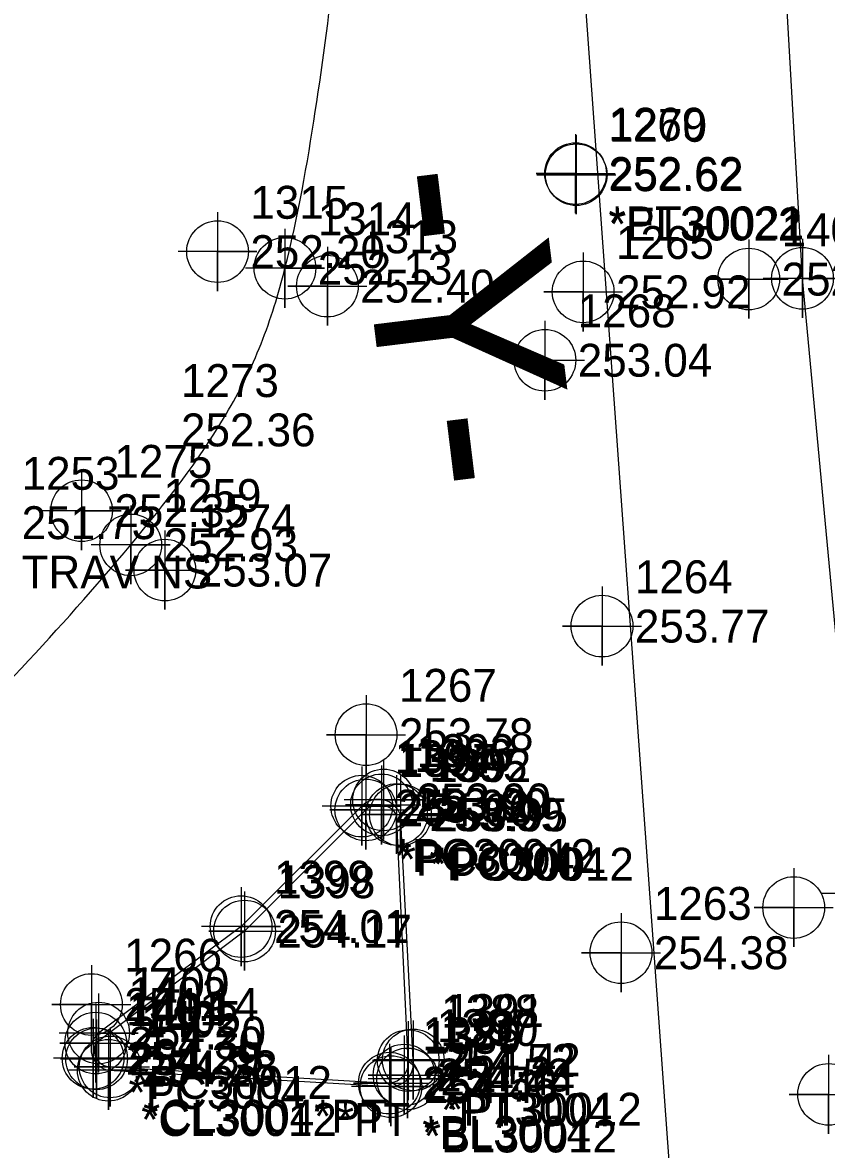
# Model space of a CAD drawing. Extents: x 2130621 to 2131998, y 642516 to 644503.
# Drawn here: x 2131200.6 to 2131261.7, y 643203.1 to 643288.8 of the extents above; entities that cross this region are included whole.
import ezdxf

# ---------------------------------------------------------------- set-up
doc = ezdxf.new("R2010")
doc.units = 0
for name, color, linetype in [('CTL Secondary Horizontal and Vertical Cogo Comment', 7, 'Continuous'), ('CTL Secondary Horizontal and Vertical Cogo Elevation', 7, 'Continuous'), ('CTL Secondary Horizontal and Vertical Cogo Number', 7, 'Continuous'), ('Exist Guardrail Cogo Elevation', 7, 'Continuous'), ('Exist Guardrail Cogo Number', 7, 'Continuous'), ('Exist Guardrail Cogo Point CELL', 7, 'Continuous'), ('Exist Roads Curbs', 7, 'Continuous'), ('Exist Roads Curbs Cogo Comment', 7, 'Continuous'), ('Exist Roads Curbs Cogo Elevation', 7, 'Continuous'), ('Exist Roads Curbs Cogo Number', 7, 'Continuous'), ('Exist Roads Curbs Cogo Point CELL', 7, 'Continuous'), ('Exist Roads EOP', 7, 'Continuous'), ('Exist Roads EOP Cogo Comment', 7, 'Continuous'), ('Exist Roads EOP Cogo Elevation', 7, 'Continuous'), ('Exist Roads EOP Cogo Number', 7, 'Continuous'), ('Exist Roads EOP Cogo Point CELL', 7, 'Continuous'), ('Exist Roads EOT Cogo Comment', 7, 'Continuous'), ('Exist Roads EOT Cogo Elevation', 7, 'Continuous'), ('Exist Roads EOT Cogo Number', 7, 'Continuous'), ('Exist Roads EOT Cogo Point CELL', 7, 'Continuous'), ('Exist Utilities Other Traffic Signal Box Cogo Elevation', 7, 'Continuous'), ('Exist Utilities Other Traffic Signal Box Cogo Number', 7, 'Continuous'), ('Prop Horizontal Alignment', 7, 'Continuous')]:
    doc.layers.add(name, color=color, linetype=linetype)

msp = doc.modelspace()

# ---------------------------------------------------------------- linework, layer by layer
at = {"layer": 'Exist Guardrail Cogo Point CELL'}
for points in [[(2131215.409, 643274.354), (2131215.409, 643268.354), (2131215.409, 643271.354), (2131218.409, 643271.354), (2131212.409, 643271.354)], [(2131205.072, 643254.664), (2131205.072, 643248.664), (2131205.072, 643251.664), (2131208.072, 643251.664), (2131202.072, 643251.664)]]:
    msp.add_lwpolyline(points, dxfattribs=at)
for centre in [(2131215.409, 643271.354), (2131205.072, 643251.664)]:
    msp.add_circle(centre, 2.344, dxfattribs=at)
at = {"layer": 'Exist Roads Curbs'}
for points in [[(2131226.681, 643228.925), (2131217.467, 643219.716), (2131206.148, 643211.206)], [(2131226.681, 643228.925), (2131226.681, 643228.925)], [(2131229.912, 643209.875), (2131229.021, 643228.574)], [(2131207.247, 643209.393), (2131228.474, 643208.158)]]:
    msp.add_lwpolyline(points, dxfattribs=at)
for centre, major_axis, ratio, start_param, end_param in [((2131227.705, 643227.782), (-1.486, 0.387), 0.999933, 3.938071, 5.698116), ((2131207.308, 643210.669), (1.277, -0.055), 0.999046, 2.750218, 4.707768), ((2131228.321, 643209.747), (-0.142, 1.59), 0.999747, 3.14801, 4.70398)]:
    msp.add_ellipse(centre, major_axis=major_axis, ratio=ratio, start_param=start_param, end_param=end_param, dxfattribs=at)
at = {"layer": 'Exist Roads Curbs Cogo Point CELL'}
for points in [[(2131226.681, 643231.925), (2131226.681, 643225.925), (2131226.681, 643228.925), (2131223.951, 643228.925), (2131229.681, 643228.925)], [(2131227.876, 643232.308), (2131227.876, 643226.308), (2131227.876, 643229.308), (2131225.146, 643229.308), (2131230.876, 643229.308)], [(2131229.021, 643231.574), (2131229.021, 643225.574), (2131229.021, 643228.574), (2131226.291, 643228.574), (2131232.021, 643228.574)], [(2131217.467, 643222.716), (2131217.467, 643216.716), (2131217.467, 643219.716), (2131214.737, 643219.716), (2131220.467, 643219.716)], [(2131206.148, 643214.206), (2131206.148, 643208.206), (2131206.148, 643211.206), (2131203.418, 643211.206), (2131209.148, 643211.206)], [(2131206.214, 643213.008), (2131206.214, 643207.008), (2131206.214, 643210.008), (2131203.484, 643210.008), (2131209.214, 643210.008)], [(2131229.912, 643212.875), (2131229.912, 643206.875), (2131229.912, 643209.875), (2131227.182, 643209.875), (2131232.912, 643209.875)], [(2131207.247, 643212.393), (2131207.247, 643206.393), (2131207.247, 643209.393), (2131204.517, 643209.393), (2131210.247, 643209.393)], [(2131228.474, 643211.158), (2131228.474, 643205.158), (2131228.474, 643208.158), (2131225.744, 643208.158), (2131231.474, 643208.158)], [(2131229.587, 643211.774), (2131229.587, 643205.774), (2131229.587, 643208.774), (2131226.857, 643208.774), (2131232.587, 643208.774)]]:
    msp.add_lwpolyline(points, dxfattribs=at)
for centre in [(2131227.876, 643229.308), (2131226.681, 643228.925), (2131229.021, 643228.574), (2131217.467, 643219.716), (2131206.148, 643211.206), (2131206.214, 643210.008), (2131229.912, 643209.875), (2131207.247, 643209.393), (2131229.587, 643208.774), (2131228.474, 643208.158)]:
    msp.add_circle(centre, 2.344, dxfattribs=at)
at = {"layer": 'Exist Roads EOP'}
for points in [[(2131264.271, 643222.565), (2131259.876, 643269.325), (2131257.02, 643319.404), (2131254.256, 643369.65), (2131250.078, 643419.419), (2131246.151, 643469.029), (2131240.838, 643519.127), (2131234.367, 643568.558), (2131226.332, 643620.181), (2131217.027, 643668.712), (2131205.621, 643717.607), (2131192.058, 643767.26), (2131177.971, 643815.091), (2131162.291, 643862.934), (2131145.36, 643910.849), (2131126.911, 643957.292), (2131112.369, 643996.123)], [(2131226.375, 643229.212), (2131217.199, 643220.058), (2131206.365, 643211.964)], [(2131226.375, 643229.212), (2131226.375, 643229.212)], [(2131230.287, 643209.923), (2131229.316, 643228.547)], [(2131207.109, 643209.139), (2131228.592, 643207.891)]]:
    msp.add_lwpolyline(points, dxfattribs=at)
for centre, major_axis, ratio, start_param, end_param in [((2131227.632, 643227.936), (-1.79, 0.066), 0.998981, 3.527087, 5.526683), ((2131207.41, 643210.728), (0.839, -1.385), 0.997672, 3.299661, 5.55015), ((2131228.533, 643209.663), (1.386, 1.107), 0.999842, 4.071754, 5.755689)]:
    msp.add_ellipse(centre, major_axis=major_axis, ratio=ratio, start_param=start_param, end_param=end_param, dxfattribs=at)
msp.add_spline([(2131166.249, 643216.695), (2131171.813, 643218.724), (2131182.371, 643223.973), (2131191.812, 643231.149), (2131200.501, 643239.699), (2131208.807, 643249.07), (2131216.067, 643259.003), (2131218.719, 643264.347), (2131220.536, 643270.096), (2131222.844, 643282.008), (2131224.358, 643293.924), (2131224.876, 643317.79), (2131222.063, 643367.672), (2131218.545, 643416.811), (2131214.319, 643466.346), (2131209.174, 643515.667), (2131202.794, 643565.155), (2131195.047, 643613.994), (2131186.401, 643662.476), (2131176.011, 643711.405), (2131164.615, 643759.89), (2131151.874, 643807.853), (2131137.855, 643855.407), (2131122.573, 643902.857), (2131105.962, 643949.486), (2131091.535, 643988.044)], degree=3, dxfattribs=at)
at = {"layer": 'Exist Roads EOP Cogo Point CELL'}
for points in [[(2131220.536, 643273.096), (2131220.536, 643267.096), (2131220.536, 643270.096), (2131223.536, 643270.096), (2131217.536, 643270.096)], [(2131259.876, 643272.325), (2131259.876, 643266.325), (2131259.876, 643269.325), (2131262.876, 643269.325), (2131256.876, 643269.325)], [(2131208.807, 643252.07), (2131208.807, 643246.07), (2131208.807, 643249.07), (2131211.807, 643249.07), (2131205.807, 643249.07)], [(2131228.036, 643232.68), (2131228.036, 643226.68), (2131228.036, 643229.68), (2131231.036, 643229.68), (2131225.036, 643229.68)], [(2131226.375, 643232.212), (2131226.375, 643226.212), (2131226.375, 643229.212), (2131229.375, 643229.212), (2131223.375, 643229.212)], [(2131229.316, 643231.547), (2131229.316, 643225.547), (2131229.316, 643228.547), (2131232.316, 643228.547), (2131226.316, 643228.547)], [(2131264.271, 643225.565), (2131264.271, 643219.565), (2131264.271, 643222.565), (2131267.271, 643222.565), (2131261.271, 643222.565)], [(2131217.199, 643223.058), (2131217.199, 643217.058), (2131217.199, 643220.058), (2131220.199, 643220.058), (2131214.199, 643220.058)], [(2131206.365, 643214.964), (2131206.365, 643208.964), (2131206.365, 643211.964), (2131209.365, 643211.964), (2131203.365, 643211.964)], [(2131205.947, 643213.044), (2131205.947, 643207.044), (2131205.947, 643210.044), (2131208.947, 643210.044), (2131202.947, 643210.044)], [(2131230.287, 643212.923), (2131230.287, 643206.923), (2131230.287, 643209.923), (2131233.287, 643209.923), (2131227.287, 643209.923)], [(2131207.109, 643212.139), (2131207.109, 643206.139), (2131207.109, 643209.139), (2131210.109, 643209.139), (2131204.109, 643209.139)], [(2131229.857, 643211.484), (2131229.857, 643205.484), (2131229.857, 643208.484), (2131232.857, 643208.484), (2131226.857, 643208.484)], [(2131228.592, 643210.891), (2131228.592, 643204.891), (2131228.592, 643207.891), (2131231.592, 643207.891), (2131225.592, 643207.891)]]:
    msp.add_lwpolyline(points, dxfattribs=at)
for centre in [(2131220.536, 643270.096), (2131259.876, 643269.325), (2131208.807, 643249.07), (2131228.036, 643229.68), (2131226.375, 643229.212), (2131229.316, 643228.547), (2131217.199, 643220.058), (2131206.365, 643211.964), (2131205.947, 643210.044), (2131230.287, 643209.923), (2131207.109, 643209.139), (2131228.592, 643207.891), (2131229.857, 643208.484)]:
    msp.add_circle(centre, 2.344, dxfattribs=at)
at = {"layer": 'Exist Roads EOT Cogo Point CELL'}
for points in [[(2131242.626, 643280.289), (2131242.626, 643274.289), (2131242.626, 643277.289), (2131239.626, 643277.289), (2131245.626, 643277.289)], [(2131242.676, 643280.201), (2131242.676, 643274.201), (2131242.676, 643277.201), (2131239.676, 643277.201), (2131245.676, 643277.201)], [(2131255.789, 643272.267), (2131255.789, 643266.267), (2131255.789, 643269.267), (2131252.789, 643269.267), (2131258.789, 643269.267)], [(2131223.758, 643271.731), (2131223.758, 643265.731), (2131223.758, 643268.731), (2131220.758, 643268.731), (2131226.758, 643268.731)], [(2131243.203, 643271.297), (2131243.203, 643265.297), (2131243.203, 643268.297), (2131240.203, 643268.297), (2131246.203, 643268.297)], [(2131240.295, 643266.099), (2131240.295, 643260.099), (2131240.295, 643263.099), (2131237.295, 643263.099), (2131243.295, 643263.099)], [(2131211.406, 643250.15), (2131211.406, 643244.15), (2131211.406, 643247.15), (2131208.406, 643247.15), (2131214.406, 643247.15)], [(2131244.636, 643245.893), (2131244.636, 643239.893), (2131244.636, 643242.893), (2131241.636, 643242.893), (2131247.636, 643242.893)], [(2131226.702, 643237.643), (2131226.702, 643231.643), (2131226.702, 643234.643), (2131223.702, 643234.643), (2131229.702, 643234.643)], [(2131259.213, 643224.506), (2131259.213, 643218.506), (2131259.213, 643221.506), (2131256.213, 643221.506), (2131262.213, 643221.506)], [(2131246.081, 643221.069), (2131246.081, 643215.069), (2131246.081, 643218.069), (2131243.081, 643218.069), (2131249.081, 643218.069)], [(2131205.819, 643217.133), (2131205.819, 643211.133), (2131205.819, 643214.133), (2131202.819, 643214.133), (2131208.819, 643214.133)], [(2131261.865, 643210.302), (2131261.865, 643204.302), (2131261.865, 643207.302), (2131258.865, 643207.302), (2131264.865, 643207.302)]]:
    msp.add_lwpolyline(points, dxfattribs=at)
for centre in [(2131242.626, 643277.289), (2131242.676, 643277.201), (2131223.758, 643268.731), (2131255.789, 643269.267), (2131243.203, 643268.297), (2131240.295, 643263.099), (2131211.406, 643247.15), (2131244.636, 643242.893), (2131226.702, 643234.643), (2131259.213, 643221.506), (2131246.081, 643218.069), (2131205.819, 643214.133), (2131261.865, 643207.302)]:
    msp.add_circle(centre, 2.344, dxfattribs=at)
at = {"layer": 'Prop Horizontal Alignment'}
msp.add_line((2131251.47, 643178.507), (2131232.752, 643436.909), dxfattribs=at)

# ---------------------------------------------------------------- texts
at = {"layer": 'CTL Secondary Horizontal and Vertical Cogo Comment'}
msp.add_text('TRAV NS', height=2.5, dxfattribs=at).set_placement((2131200.518, 643245.754))
at = {"layer": 'CTL Secondary Horizontal and Vertical Cogo Elevation'}
msp.add_text('251.73', height=2.5, dxfattribs=at).set_placement((2131200.518, 643249.504))
at = {"layer": 'CTL Secondary Horizontal and Vertical Cogo Number'}
msp.add_text('1253', height=2.5, dxfattribs=at).set_placement((2131200.518, 643253.254))
at = {"layer": 'Exist Guardrail Cogo Elevation'}
for s, p in [('252.20', (2131217.909, 643270.104)), ('252.35', (2131207.572, 643250.414))]:
    msp.add_text(s, height=2.5, dxfattribs=at).set_placement(p)
at = {"layer": 'Exist Guardrail Cogo Number'}
for s, p in [('1315', (2131217.909, 643273.854)), ('1275', (2131207.572, 643254.164))]:
    msp.add_text(s, height=2.5, dxfattribs=at).set_placement(p)
at = {"layer": 'Exist Roads Curbs Cogo Comment'}
for s, p in [('*PC3004', (2131229.181, 643223.925)), ('*PC3004', (2131231.521, 643223.574)), ('*PC3004', (2131208.648, 643206.206)), ('*CL3004*PT', (2131209.747, 643204.393)), ('*PT3004', (2131232.412, 643204.875)), ('*BL3004', (2131230.974, 643203.158))]:
    msp.add_text(s, height=2.5, dxfattribs=at).set_placement(p)
at = {"layer": 'Exist Roads Curbs Cogo Elevation'}
for s, p in [('254.00', (2131229.181, 643227.675)), ('253.99', (2131230.376, 643228.058)), ('253.99', (2131231.521, 643227.324)), ('254.17', (2131219.967, 643218.466)), ('254.30', (2131208.648, 643209.956)), ('254.35', (2131208.714, 643208.758)), ('254.52', (2131232.412, 643208.625)), ('254.38', (2131209.747, 643208.143)), ('254.56', (2131230.974, 643206.908)), ('254.53', (2131232.087, 643207.524))]:
    msp.add_text(s, height=2.5, dxfattribs=at).set_placement(p)
at = {"layer": 'Exist Roads Curbs Cogo Number'}
for s, p in [('1396', (2131230.376, 643231.808)), ('1397', (2131229.181, 643231.425)), ('1395', (2131231.521, 643231.074)), ('1398', (2131219.967, 643222.216)), ('1403', (2131208.648, 643213.706)), ('1404', (2131208.714, 643212.508)), ('1388', (2131232.412, 643212.375)), ('1405', (2131209.747, 643211.893)), ('1387', (2131232.087, 643211.274)), ('1386', (2131230.974, 643210.658))]:
    msp.add_text(s, height=2.5, dxfattribs=at).set_placement(p)
at = {"layer": 'Exist Roads EOP Cogo Comment'}
for s, p in [('*PC30012', (2131228.875, 643224.212)), ('*PC30012', (2131231.816, 643223.547)), ('*PC30012', (2131208.865, 643206.964)), ('*PT30012', (2131232.787, 643204.923)), ('*CL30012*PT', (2131209.609, 643204.139)), ('*BL30012', (2131231.092, 643202.891))]:
    msp.add_text(s, height=2.5, dxfattribs=at).set_placement(p)
at = {"layer": 'Exist Roads EOP Cogo Elevation'}
for s, p in [('252.13', (2131223.036, 643268.846)), ('252.93', (2131211.307, 643247.82)), ('253.90', (2131230.536, 643228.43)), ('253.92', (2131228.875, 643227.962)), ('253.95', (2131231.816, 643227.297)), ('254.01', (2131219.699, 643218.808)), ('254.20', (2131208.865, 643210.714)), ('254.29', (2131208.447, 643208.794)), ('254.42', (2131232.787, 643208.673)), ('254.26', (2131209.609, 643207.889)), ('254.44', (2131232.357, 643207.234)), ('254.43', (2131231.092, 643206.641))]:
    msp.add_text(s, height=2.5, dxfattribs=at).set_placement(p)
at = {"layer": 'Exist Roads EOP Cogo Number'}
for s, p in [('1314', (2131223.036, 643272.596)), ('1259', (2131211.307, 643251.57)), ('1394', (2131228.875, 643231.712)), ('1393', (2131230.536, 643232.18)), ('1392', (2131231.816, 643231.047)), ('1399', (2131219.699, 643222.558)), ('1400', (2131208.865, 643214.464)), ('1401', (2131208.447, 643212.544)), ('1391', (2131232.787, 643212.423)), ('1402', (2131209.609, 643211.639)), ('1389', (2131231.092, 643210.391)), ('1390', (2131232.357, 643210.984))]:
    msp.add_text(s, height=2.5, dxfattribs=at).set_placement(p)
at = {"layer": 'Exist Roads EOT Cogo Comment'}
for s, p in [('*PT30021', (2131245.126, 643272.289)), ('*EL30022', (2131245.176, 643272.201))]:
    msp.add_text(s, height=2.5, dxfattribs=at).set_placement(p)
at = {"layer": 'Exist Roads EOT Cogo Elevation'}
for s, p in [('252.62', (2131245.126, 643276.039)), ('252.62', (2131245.176, 643275.951)), ('252.83', (2131258.289, 643268.017)), ('252.40', (2131226.258, 643267.481)), ('252.92', (2131245.703, 643267.047)), ('253.04', (2131242.795, 643261.849)), ('253.07', (2131213.906, 643245.9)), ('253.77', (2131247.136, 643241.643)), ('253.78', (2131229.202, 643233.393)), ('254.38', (2131248.581, 643216.819)), ('254.14', (2131208.319, 643212.883))]:
    msp.add_text(s, height=2.5, dxfattribs=at).set_placement(p)
at = {"layer": 'Exist Roads EOT Cogo Number'}
for s, p in [('1269', (2131245.126, 643279.789)), ('1270', (2131245.176, 643279.701)), ('1313', (2131226.258, 643271.231)), ('1406', (2131258.289, 643271.767)), ('1265', (2131245.703, 643270.797)), ('1268', (2131242.795, 643265.599)), ('1274', (2131213.906, 643249.65)), ('1264', (2131247.136, 643245.393)), ('1267', (2131229.202, 643237.143)), ('1263', (2131248.581, 643220.569)), ('1266', (2131208.319, 643216.633))]:
    msp.add_text(s, height=2.5, dxfattribs=at).set_placement(p)
at = {"layer": 'Exist Utilities Other Traffic Signal Box Cogo Elevation'}
msp.add_text('252.36', height=2.5, dxfattribs=at).set_placement((2131212.635, 643256.553))
at = {"layer": 'Exist Utilities Other Traffic Signal Box Cogo Number'}
msp.add_text('1273', height=2.5, dxfattribs=at).set_placement((2131212.635, 643260.303))
at = {"layer": 'Prop Horizontal Alignment'}
msp.add_text('-Y-', height=14, rotation=276.97284, dxfattribs=at).set_placement((2131225.885, 643277.339))

doc.saveas('drawing.dxf')
